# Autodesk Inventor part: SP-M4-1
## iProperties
Author: Ron Crain
Shininess: 85.0
Length Units: 11269
Angle Units: 11284
Time Units: 11279
Mass Units: 11290
Length Display Precision: 2
Angle Display Precision: 1
Compacted: True
PropertySet Name: _Private Model Information
Created: 2001-02
Part Number: SP-M4-1
Material: Stainless Steel, Austenitic
Description: NUT, SELF CLINCH, TYPE SP, M4x0.7
Vendor: PENN MFG. & ENG
Document SubType Name: Modeling
Designer: Ron Crain
Control State: 0
Master: False
Checked Out: False
PropertySet Name: Design Tracking Control
Density: 0.0
Volumn: 0.0
Area: 0.0
PropertySet Name: Model Information
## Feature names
1. Revolution1
